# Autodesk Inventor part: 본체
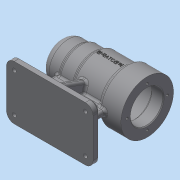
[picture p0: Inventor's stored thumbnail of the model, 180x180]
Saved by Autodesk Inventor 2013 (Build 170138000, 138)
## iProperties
Created: 2016-06
Part Number: 본체
Material: 일반
Document SubType Name: Modeling
Designer: Administrator
Density: 1 g/cm^3
Author: Administrator
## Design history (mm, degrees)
sketch "스케치1"
  geometry: L1 (-112, 0)-(-112, 25); L2 (-112, 25)-(-87, 25); L3 (-87, 25)-(-87, 27); L4 (-87, 27)-(-67, 27); L5 (-67, 27)-(-67, 30); L6 (-67, 30)-(-28, 30); L7 (-28, 30)-(-28, 34); L8 (-28, 34)-(0, 34); L9 (0, 34)-(0, 0); L10 (0, 0)-(-112, 0)
  constraints: 20 end point, 8 parallel, 1 perpendicular, 1 vertical
  dimensions: "d0" = 50 diameter of L2 L10; "d2" = 54 diameter of L4 L10; "d3" = 60 diameter of L6 L10; "d4" = 68 diameter of L8 L10; "d5" = 25 distance of L1.end L2.end; "d6" = 45 distance between parallel lines of L5 L1; "d7" = 84 distance between parallel lines of L7 L1; "d8" = 112 distance between parallel lines of L9 L1
revolve "회전1" sketch "스케치1" stored, may be unused: angle "d9" = 90 deg
fillet "모깎기1" dims "d10" = 10
fillet "모깎기2" dims "d11" = 3
sketch "스케치2"
  geometry: L1 (-35, -60)-(35, -60); L2 (35, -60)-(35, -70); L3 (35, -70)-(-35, -70); L4 (-35, -70)-(-35, -60); C1 r 34 at (0, 0) reference; 1 further point
  constraints: 8 end point, 2 parallel, 1 horizontal, 1 midpoint, 1 perpendicular, 1 vertical alignment
  dimensions: "d12" = 10 distance of L3.end L1.start; "d14" = 70 distance from line of C1.centre L3; "d15" = 70 distance of L2.end L3.end
extrude "돌출1" join sketch "스케치2" distance "d16" = 112; taper "d17" = 0 deg
sketch "스케치3"
  geometry: L1 (-31, -30)-(-64.804, -30) reference; L2 (-70, -27)-(-85.356, -27) reference; L3 (-89.828, -25)-(-102, -25) reference; L4 (-112, -15)-(-112, 15) reference; L5 (-102, 25)-(-89.828, 25) reference; L6 (-85.356, 27)-(-70, 27) reference; L7 (-64.804, 30)-(-31, 30) reference; L8 (-25.343, 34)-(0, 34) reference; L9 (0, 34)-(0, -34) reference; L10 (0, -34)-(-25.343, -34) reference; L11 (-112, -60)-(0, -60) reference; L12 (0, -60)-(0, -70) reference; L13 (0, -70)-(-112, -70) reference; L14 (-112, -70)-(-112, -60) reference; L15 (-92, -60)-(-92, 0); L16 (-20, -60)-(-20, 0); L17 (-92, 0)-(-20, 0); A1 r 3 centre (-25.343, -31) between (-28.172, -32) and (-25.343, -34) reference; A2 r 3 centre (-31, -33) between (-28.172, -32) and (-31, -30) reference; A3 r 3 centre (-64.804, -27) between (-67.402, -28.5) and (-64.804, -30) reference; A4 r 3 centre (-70, -30) between (-67.402, -28.5) and (-70, -27) reference; A5 r 3 centre (-85.356, -24) between (-87.592, -26) and (-85.356, -27) reference; A6 r 3 centre (-89.828, -28) between (-87.592, -26) and (-89.828, -25) reference; A7 r 10 centre (-102, -15) between (-112, -15) and (-102, -25) reference; A8 r 10 centre (-102, 15) between (-102, 25) and (-112, 15) reference; A9 r 3 centre (-89.828, 28) between (-89.828, 25) and (-87.592, 26) reference; A10 r 3 centre (-85.356, 24) between (-85.356, 27) and (-87.592, 26) reference; A11 r 3 centre (-70, 30) between (-70, 27) and (-67.402, 28.5) reference; A12 r 3 centre (-64.804, 27) between (-64.804, 30) and (-67.402, 28.5) reference; A13 r 3 centre (-31, 33) between (-31, 30) and (-28.172, 32) reference; A14 r 3 centre (-25.343, 31) between (-25.343, 34) and (-28.172, 32) reference; 2 further points
  constraints: 6 end point, 2 parallel, 2 point on line, 1 horizontal alignment, 1 midpoint, 1 perpendicular
  dimensions: "d18" = 20 distance between parallel lines of L12 L16; "d19" = 20 distance between parallel lines of L14 L15
extrude "돌출2" join sketch "스케치3" stored distance "d20" = 8; taper "d21" = 0 deg
node "작업 평면1"
sketch "스케치4"
  geometry: L1 (-35, -70)-(-35, -60) reference; L2 (-35, -60)-(-4, -60) reference; L3 (-4, -60)-(-4, -29.732) reference; L4 (4, -29.732)-(4, -60) reference; L5 (4, -60)-(35, -60) reference; L6 (35, -60)-(35, -70) reference; L7 (35, -70)-(-35, -70) reference; L8 (28, -60)-(6.162, 0); L9 (-28, -60)-(-6.162, 0); L10 (-6.162, 0)-(6.162, 0); A1 r 30 centre (0, 0) between (4, -29.732) and (-4, -29.732) reference; 1 further point
  constraints: 6 end point, 2 horizontal alignment, 2 point on line, 1 parallel
  dimensions: "d23" = 110 deg angle of L5 L8; "d24" = 110 deg angle of L2 L9; "d25" = 7 distance from line of L9.start L1; "d26" = 7 distance from line of L6 L8.start
extrude "돌출3" join sketch "스케치4" stored distance "d27" = 8; taper "d28" = 0 deg
sketch "스케치5"
  geometry: L1 (0, 26)-(0, -26); L2 (-26, 0)-(26, 0); C1 r 34 at (0, 0) reference; 5 further points
  constraints: 5 coincident, 4 end point, 2 midpoint, 2 perpendicular, 1 vertical
  dimensions: "d29" = 52 distance of L2.start L2.end
hole "구멍1" sketch "스케치5" at (0, 26), (-26, 0), (0, -26), (26, 0) diameter "d31" = 3.242; stored, may be unused: countersink angle "d35" = 90 deg, drill point angle "d37" = 118 deg; dims "d32" = 8, "d33" = 4, "d34" = 2, "d36" = 11
sketch "스케치6"
  geometry: L1 (0, 70)-(-112, 70) reference; L2 (-112, 0)-(-112, 70) reference; L3 (-102, 60)-(-10, 60); L4 (-10, 60)-(-10, 10); L5 (-10, 10)-(-102, 10); L6 (-102, 10)-(-102, 60); 9 further points
  constraints: 8 end point, 4 coincident, 4 midpoint, 2 parallel, 1 horizontal, 1 horizontal alignment, 1 perpendicular, 1 vertical alignment
  dimensions: "d38" = 92 distance of L4.end L5.end; "d40" = 50 distance of L5.end L3.start
hole "구멍2" sketch "스케치6" at (-102, 60), (-10, 60), (-102, 10), (-10, 10) diameter "d41" = 5; stored, may be unused: countersink angle "d45" = 90 deg, drill point angle "d47" = 118 deg; dims "d42" = 5, "d43" = 9, "d44" = 4, "d46" = 11
node "작업 평면2"
sketch "스케치7"
  geometry: L1 (0, -34)-(0, 34) reference; 3 further points
  constraints: 1 horizontal alignment, 1 midpoint, 1 other
  dimensions: "d49" = 48 distance from line of L1 point (-48, 0)
feature "엠보싱1" sketch "스케치7" dims "d50" = 0.5, "d51" = 0
fillet "모깎기3" dims "d52" = 10
sketch "스케치8"
  geometry: L1 (-25.343, 34)-(0, 34) reference; L2 (0, 34)-(0, 27.621) reference; L3 (0, 27.621)-(-11, 27.621) reference; L4 (-11, 27.621)-(-11.974, 26) reference; L5 (-11.974, 26)-(-11, 24.379) reference; L6 (-11, 24.379)-(0, 24.379) reference; L7 (0, 24.379)-(0, -24.379) reference; L8 (0, -24.379)-(-11, -24.379) reference; L9 (-11, -24.379)-(-11.974, -26) reference; L10 (-11.974, -26)-(-11, -27.621) reference; L11 (-11, -27.621)-(0, -27.621) reference; L12 (0, -27.621)-(0, -34) reference; L13 (0, -34)-(-20, -34) reference; L14 (-20, -34)-(-20, -60) reference; L15 (-20, -60)-(0, -60) reference; L16 (0, -60)-(0, -70) reference; L17 (0, -70)-(-112, -70) reference; L18 (-112, -70)-(-112, -60) reference; L19 (-112, -60)-(-92, -60) reference; L20 (-92, -60)-(-92, -25) reference; L21 (-92, -25)-(-102, -25) reference; L22 (-112, -15)-(-112, 15) reference; L23 (-102, 25)-(-89.828, 25) reference; L24 (-85.356, 27)-(-70, 27) reference; L25 (-64.804, 30)-(-31, 30) reference; L26 (-106, 0)-(-106, 10.5); L27 (-106, 10.5)-(-103, 10.5); L28 (-103, 10.5)-(-103, 16); L29 (-103, 16)-(-99, 16); L30 (-99, 16)-(-99, 17.5); L31 (-99, 17.5)-(-81, 17.5); L32 (-81, 17.5)-(-81, 21); L33 (-81, 21)-(-69, 21); L34 (-69, 21)-(-69, 24); L35 (-69, 24)-(-15, 24); L36 (-15, 24)-(-15, 21); L37 (-15, 21)-(0, 21); L38 (-106, 0)-(0, 0); A1 r 3 centre (-25.343, 31) between (-25.343, 34) and (-28.172, 32) reference; A2 r 10 centre (-102, -15) between (-112, -15) and (-102, -25) reference; A3 r 10 centre (-102, 15) between (-102, 25) and (-112, 15) reference; A4 r 3 centre (-89.828, 28) between (-89.828, 25) and (-87.592, 26) reference; A5 r 3 centre (-85.356, 24) between (-85.356, 27) and (-87.592, 26) reference; A6 r 3 centre (-70, 30) between (-70, 27) and (-67.402, 28.5) reference; A7 r 3 centre (-64.804, 27) between (-64.804, 30) and (-67.402, 28.5) reference; A8 r 3 centre (-31, 33) between (-31, 30) and (-28.172, 32) reference
  constraints: 26 end point, 8 parallel, 5 perpendicular, 1 point on line
  dimensions: "d53" = 3 distance of L26.end L27.end; "d55" = 4 distance of L28.end L29.end; "d56" = 18 distance of L30.end L31.end; "d57" = 12 distance of L32.end L33.end; "d58" = 54 distance of L34.end L35.end; "d59" = 15 distance of L36.end L37.end; "d60" = 42 diameter of L37 L38; "d61" = 48 diameter of L35 L38; "d62" = 42 diameter of L33 L38; "d63" = 35 diameter of L31 L38; "d64" = 32 diameter of L29 L38; "d65" = 21 diameter of L27 L38
revolve "회전2" sketch "스케치8" stored, may be unused: angle "d66" = 90 deg
fillet "모깎기4" dims "d67" = 3
fillet "모깎기5" dims "d68" = 0.3
fillet "모깎기6" dims "d69" = 3
chamfer "모따기1" distance "d70" = 1; stored, may be unused: second distance "d71" = 2, angle "d72" = 45 deg
fillet "모깎기7" dims "d73" = 3
fillet "모깎기9" dims "d75" = 3
chamfer "모따기2" distance "d76" = 4; stored, may be unused: second distance "d77" = 2, angle "d78" = 45 deg
node "솔리드1"
node "절단 모서리 투영1"
node "절단 모서리 투영2"
node "절단 모서리 투영3"
other parameters: "d48" = 98.75
